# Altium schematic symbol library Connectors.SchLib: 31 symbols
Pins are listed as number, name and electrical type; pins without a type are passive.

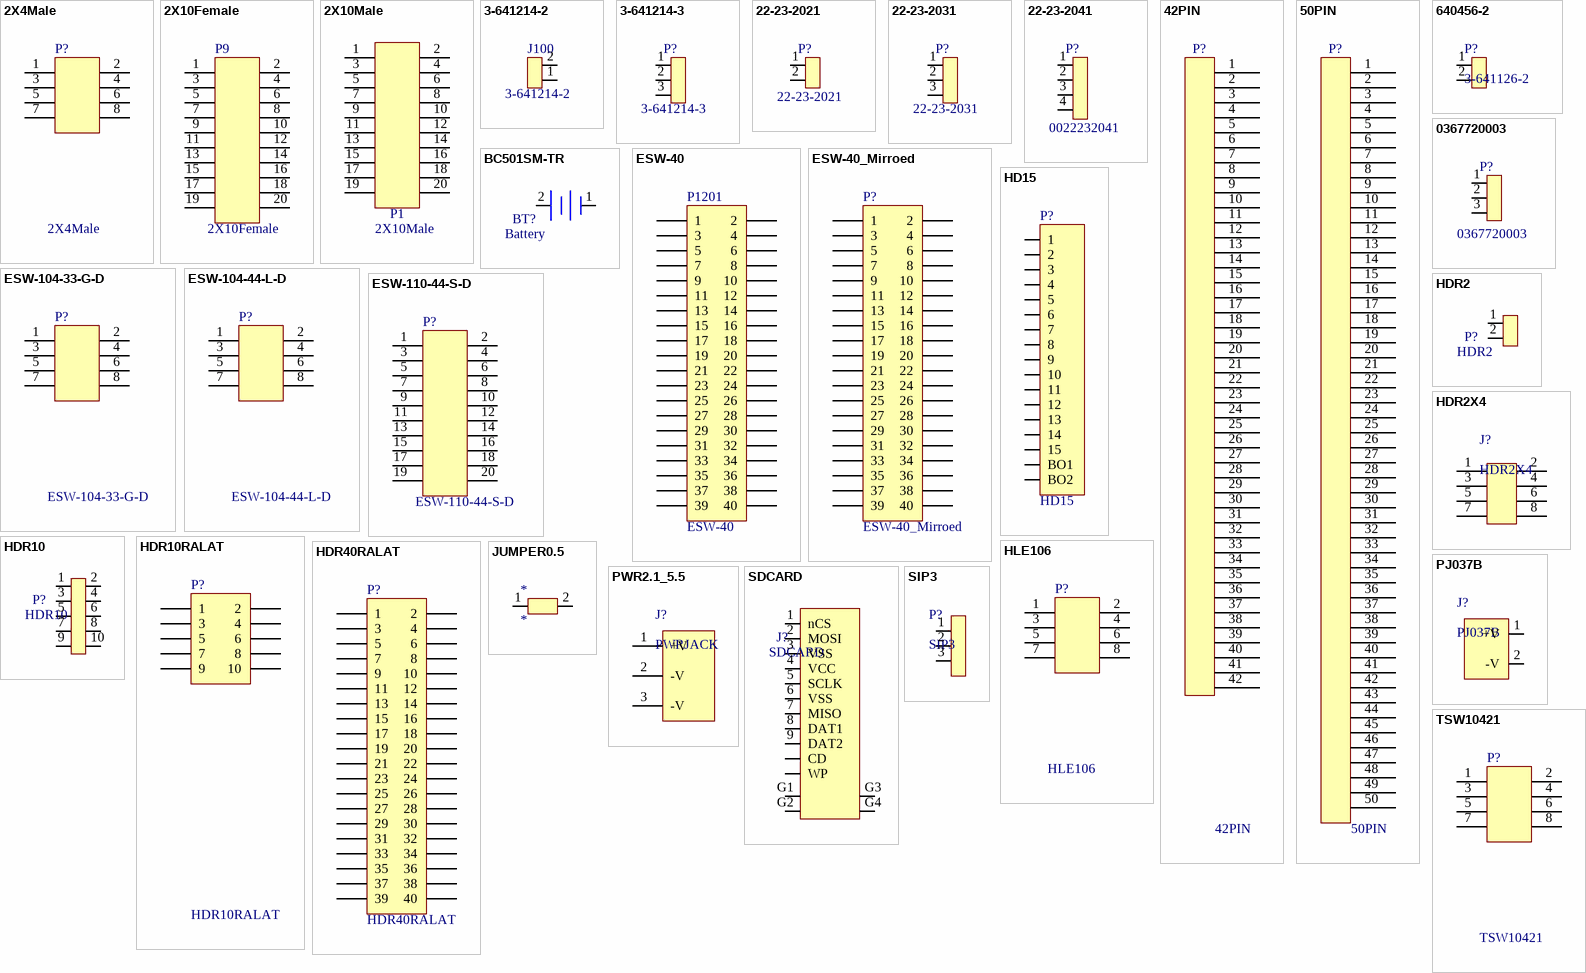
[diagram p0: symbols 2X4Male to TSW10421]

## 2X4Male
designator P?
Connector Header Through Hole 8 position 0.100" (2.54mm); MFG PN: PRPC004DAAN-RC; DK PN: S2011EC-04-ND; MFG: Sullins
footprint HDR2X4
pins: 1, 2, 3, 4, 5, 6, 7, 8

## 2X10Female
designator P9
CONN HEADER FEM 20POS.1" DL GOLD; MFG PN: PPPC102LFBN-RC; DK PN: S6106-ND; MFG: Sullins
footprint HDR2X10
pins: 1, 2, 3, 4, 5, 6, 7, 8, 9, 10, 11, 12, 13, 14, 15, 16, 17, 18, 19, 20

## 2X10Male
designator P1
Connector Header Through Hole 20 position 0.100" (2.54mm); MFG PN: PRPC010DAAN-RC; DK PN: S2011EC-10-ND; MFG: Sullins
footprint HDR2X10
pins: 1, 2, 3, 4, 5, 6, 7, 8, 9, 10, 11, 12, 13, 14, 15, 16, 17, 18, 19, 20

## 3-641214-2
designator J100
CONN HEADER RT/A .100 2POS 30AU; DK PN: A30778-ND; MFG: TE Connectivity
footprint 3-641214-2
pins: 1, 2

## 3-641214-3
designator P?  Comment_1: 3-641214-3  (hidden comment: *)
CONN HEADER RT/A .100 3POS 30AU; DK PN: A30779-ND; MFG: TE Connectivity
footprint 3-641214-3
pins: 1, 2, 3

## 22-23-2021
designator P?  Comment_1: 22-23-2021  (hidden comment: *)
CONN HEADER VERT .100 2POS 30AU; DK PN: WM4200-ND; MFG: TE Connectivity
footprint 22-23-2021 (Footprint not found)
pins: 1, 2

## 22-23-2031
designator P?  Comment_1: 22-23-2031  (hidden comment: *)
CONN HEADER VERT .100 3POS 30AU; DK PN: WM4201-ND; MFG: TE Connectivity
footprint 22-23-2031
pins: 1, 2, 3

## 22-23-2041
designator P?  Comment_1: 0022232041  (hidden comment: *)
Connector Header Through Hole 4 position 0.100" (2.54mm); DK PN: WM4202-ND; MFG: TE Connectivity
footprint 22-23-2041
pins: 1, 2, 3, 4

## 42PIN
designator P?
footprint IDC42
pins: 1, 2, 3, 4, 5, 6, 7, 8, 9, 10, 11, 12, 13, 14, 15, 16, 17, 18, 19, 20, 21, 22, 23, 24, 25, 26, 27, 28, 29, 30, 31, 32, 33, 34, 35, 36, 37, 38, 39, 40, 41, 42

## 50PIN
designator P?
footprint IDC50
footprint IDC50_40
pins: 1, 2, 3, 4, 5, 6, 7, 8, 9, 10, 11, 12, 13, 14, 15, 16, 17, 18, 19, 20, 21, 22, 23, 24, 25, 26, 27, 28, 29, 30, 31, 32, 33, 34, 35, 36, 37, 38, 39, 40, 41, 42, 43, 44, 45, 46, 47, 48, 49, 50

## 640456-2
designator P?, comment 3-641126-2
CONN HEADER VERT 2POS .100 GOLD; DK PN: A113510-ND; MFG: TE Connectivity
footprint 640456-2
pins: 1, 2

## 0367720003
designator P?
CONN HEADER VERT 3POS 3.96MM; DK PN: WM20030-ND; MFG: TE Connectivity
footprint 3-641214-2
pins: 1, 2, 3

## BC501SM-TR
designator BT?, comment Battery
Battery Holder (Open) Coin, 12.0mm 1 Cell SMD (SMT) Tab; MFG: MPD; MFG PN: BC501SM-TR; DK PN: BC501SM-TR-ND
footprint BC501SM
pins: 1, 2

## ESW-40
designator P1201
40 Position Elevated Socket Connector 0.100" (2.54mm) Through Hole Gold; MFG: Samtec; MFG PN: ESW-120-33-G-D; DK PN: SAM9012-ND
footprint HDR2X20 (Connector; Header; 20x2 Position)
pins: 1, 2, 3, 4, 5, 6, 7, 8, 9, 10, 11, 12, 13, 14, 15, 16, 17, 18, 19, 20, 21, 22, 23, 24, 25, 26, 27, 28, 29, 30, 31, 32, 33, 34, 35, 36, 37, 38, 39, 40

## ESW-40_Mirroed
designator P?
40 Position Elevated Socket Connector 0.100" (2.54mm) Through Hole Gold; MFG: Samtec; MFG PN: ESW-120-33-G-D; DK PN: SAM9012-ND
footprint HDR2X20-Mirrored (Connector; Header; 20x2 Position)
pins: 1, 2, 3, 4, 5, 6, 7, 8, 9, 10, 11, 12, 13, 14, 15, 16, 17, 18, 19, 20, 21, 22, 23, 24, 25, 26, 27, 28, 29, 30, 31, 32, 33, 34, 35, 36, 37, 38, 39, 40

## ESW-104-33-G-D
designator P?
8 Position Elevated Socket Connector Through Hole; DK PN: ESW-104-33-G-D-ND; MFG: Samtec
footprint HDR2X4
pins: 1, 2, 3, 4, 5, 6, 7, 8

## ESW-104-44-L-D
designator P?
8 Position Elevated Socket Connector Through Hole; DK PN: ESW-104-44-L-D-ND; MFG: Samtec
footprint HDR2X4
pins: 1, 2, 3, 4, 5, 6, 7, 8

## ESW-110-44-S-D
designator P?
20 Position Elevated Socket Connector Through Hole; DK PN: SAM11133-ND; MFG: Samtec
footprint HDR2X10
pins: 1, 2, 3, 4, 5, 6, 7, 8, 9, 10, 11, 12, 13, 14, 15, 16, 17, 18, 19, 20

## HD15
designator P?
CONN DSUB HD RCPT 15POS R/A SLDR; Text Field1: Amphenol; Text Field2: ICD15S13E4GX00LF; Text Field3: 609-5181-ND
footprint DB15FLC
pins: 1, 2, 3, 4, 5, 6, 7, 8, 9, 10, 11, 12, 13, 14, 15, BO1, BO2

## HDR2
designator P?
footprint HDR2
pins: 1, 2

## HDR2X4
designator J?
footprint HDR2X4
pins: 1, 2, 3, 4, 5, 6, 7, 8

## HDR10
designator P?
footprint HDR2
pins: 1, 2, 3, 4, 5, 6, 7, 8, 9, 10

## HDR10RALAT
designator P?
Connector Header Through Hole, Right Angle 10 position 0.100" (2.54mm); MFG: 3M; MFG PN: N3793-5202RB; DK PN: MHR10S-ND
footprint HDR10RALAT
pins: 1, 2, 3, 4, 5, 6, 7, 8, 9, 10

## HDR40RALAT
designator P?
Connector Header Through Hole, Right Angle 40 position 0.100" (2.54mm); MFG: 3M; MFG PN: N3432-5202RB; DK PN: MHR40S-ND
footprint HDR40RALAT
pins: 1, 2, 3, 4, 5, 6, 7, 8, 9, 10, 11, 12, 13, 14, 15, 16, 17, 18, 19, 20, 21, 22, 23, 24, 25, 26, 27, 28, 29, 30, 31, 32, 33, 34, 35, 36, 37, 38, 39, 40

## HLE106
designator P?
8 Position Receptacle, Bottom Entry Connector Surface Mount; MFG PN: HLE-104-02-L-DV-BE-K-TR; DK PN: SAM13991CT-ND; MFG: Samtec
footprint HLE-PEBE8
pins: 1, 2, 3, 4, 5, 6, 7, 8

## JUMPER0.5
designator *
footprint JUMPER0.5
pins: 1, 2

## PJ037B
designator J?  Comment_1: PJ037B  (hidden comment: *)
Power Barrel Connector Jack 2.50mm ID (0.098"), 5.50mm OD (0.217") Through Hole, Right Angle; MFG PN: PJ-037B; DK PN: CP-037B-ND; MFG: CUI
footprint PJ037B
pins: 1 +V, 2 -V
1 alternate drawing of the same symbol

## PWR2.1_5.5
designator J?  Comment_1: PWRJACK  (hidden comment: *)
Power Barrel Connector Jack 2.10mm ID (0.083"), 5.50mm OD (0.217") Through Hole, Right Angle; MFG PN: EJ503A; DK PN: EJ503A-ND; MFG: Memory Protection Devices
footprint EJ503A
pins: 1 +V, 2 -V, 3 -V (power)
1 alternate drawing of the same symbol

## SDCARD
designator J?
11 (9 + 2) Position Card Connector Secure Digital - SD Surface Mount, Right Angle Gold; MFG: TE; MFG PN: 2041021-4; DK PN: A101492CT-ND
footprint SDCARD2041021
pins: 1 nCS, 2 MOSI, 3 VSS, 4 VCC, 5 SCLK, 6 VSS, 7 MISO, 8 DAT1, 9 DAT2, CD, G1, G2, G3, G4, WP

## SIP3
designator P?
footprint SIP3
pins: 1, 2, 3

## TSW10421
designator P?
Connector Header Through Hole 8 position 0.100" (2.54mm); MFG PN: HTSW-104-21-G-D-ND; MFG: Samtec
footprint HDR2X4
pins: 1, 2, 3, 4, 5, 6, 7, 8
